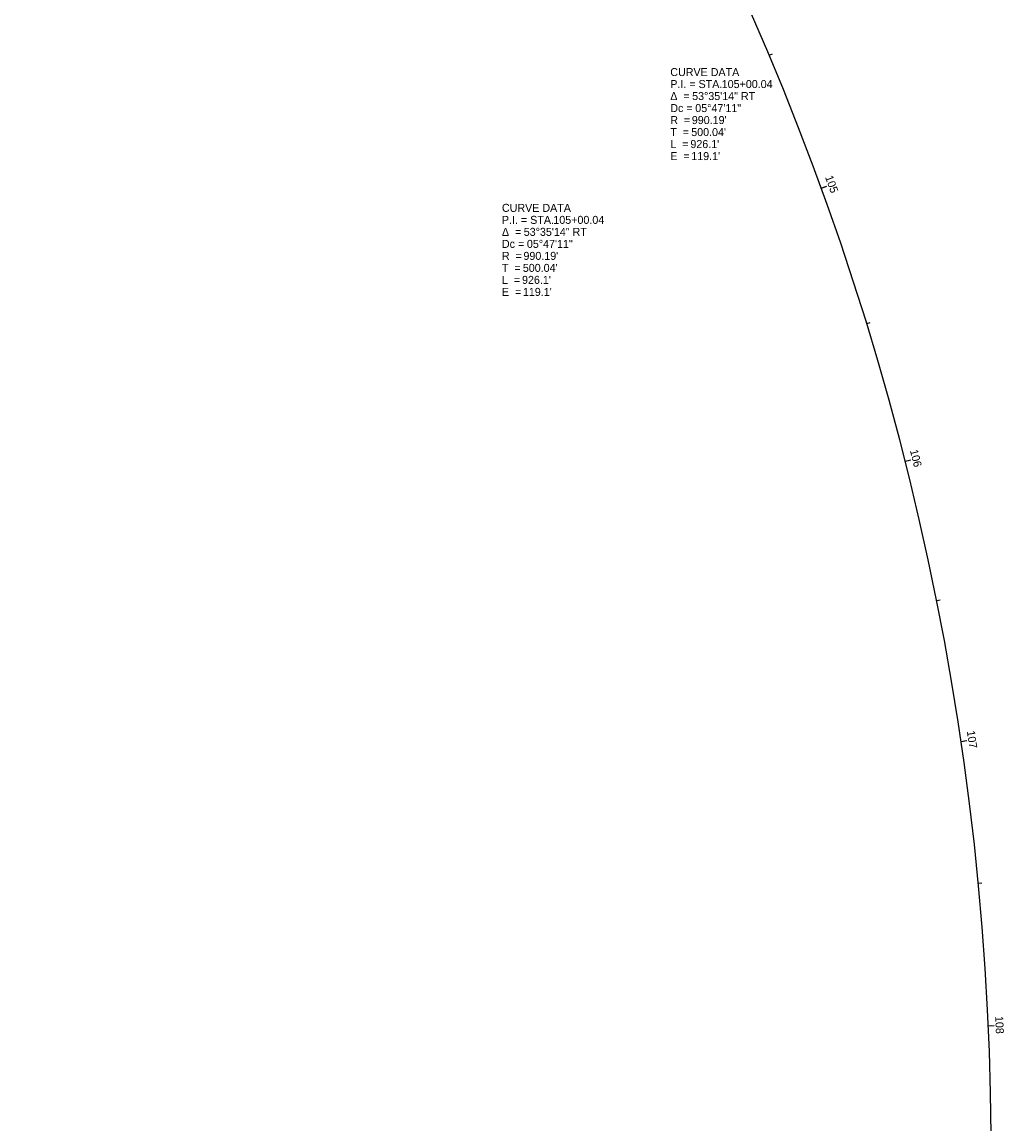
# Model space of a CAD drawing. Extents: x 1392427 to 1392809, y 435950 to 439080.
# Drawn here: x 1392427.6 to 1392771.2, y 438309.3 to 438694.9 of the extents above; entities that cross this region are included whole.
import ezdxf

# ---------------------------------------------------------------- set-up
doc = ezdxf.new("R2010")
doc.units = 0
for name, color, linetype in [('Default', 7, 'Continuous'), ('PV_X_Curb', 7, 'Continuous'), ('PV_X_EOP', 7, 'Continuous'), ('RD_X_Cells', 7, 'Continuous'), ('RW_X_CL', 7, 'Continuous'), ('RW_X_CL_100_Curve_Data', 7, 'Continuous'), ('RW_X_CL_100_Stations', 7, 'Continuous'), ('SV_X_Mon_Cells_Found', 7, 'Continuous'), ('SV_X_Random_Point', 7, 'Continuous'), ('VG_X_Cells', 7, 'Continuous')]:
    doc.layers.add(name, color=color, linetype=linetype)

msp = doc.modelspace()

# ---------------------------------------------------------------- linework, layer by layer
at = {"layer": 'Default'}
msp.add_arc((1391776.54, 438298.83), 990.19, 355.29887, 48.88602, dxfattribs=at)
at = {"layer": 'PV_X_Curb'}
for p, q in [((1392707.29, 438636.75), (1392709.17, 438637.43)), ((1392736.61, 438541.19), (1392737.78, 438541.49)), ((1392756.16, 438443.17), (1392757.34, 438443.34)), ((1392765.72, 438343.67), (1392766.92, 438343.72))]:
    msp.add_line(p, q, dxfattribs=at)
at = {"layer": 'RD_X_Cells'}
msp.add_line((1392707.29, 438636.75), (1392708.41, 438637.16), dxfattribs=at)
at = {"layer": 'RW_X_CL'}
msp.add_arc((1391776.54, 438298.83), 990.19, 355.29887, 48.88602, dxfattribs=at)
msp.add_arc((1391776.54, 438298.83), 990.19, 355.29887, 48.88602, dxfattribs=at)
at = {"layer": 'RW_X_CL_100_Stations'}
for p, q in [((1392689.04, 438683.3), (1392690.15, 438683.77)), ((1392707.29, 438636.75), (1392709.17, 438637.43)), ((1392723.16, 438589.34), (1392724.3, 438589.7)), ((1392736.61, 438541.19), (1392738.55, 438541.68)), ((1392747.62, 438492.43), (1392748.8, 438492.66)), ((1392756.16, 438443.17), (1392758.13, 438443.46)), ((1392762.19, 438393.54), (1392763.39, 438393.65)), ((1392765.72, 438343.67), (1392767.71, 438343.76))]:
    msp.add_line(p, q, dxfattribs=at)
at = {"layer": 'SV_X_Mon_Cells_Found'}
for p, q in [((1392707.29, 438636.75), (1392709.17, 438637.43)), ((1392736.61, 438541.19), (1392737.78, 438541.49)), ((1392756.16, 438443.17), (1392757.34, 438443.34)), ((1392765.72, 438343.67), (1392766.92, 438343.72))]:
    msp.add_line(p, q, dxfattribs=at)

# ---------------------------------------------------------------- texts
at = {"layer": 'PV_X_Curb'}
msp.add_text('105', height=2.8, rotation=289.9544, dxfattribs=at).set_placement((1392708.54, 438640.62))
at = {"layer": 'PV_X_EOP'}
for s, p in [('CURVE DATA', (1392595.53, 438628.46)), ('P.I. = STA. ', (1392595.53, 438624.26)), ('105+00.04', (1392613.52, 438624.26)), ('Δ  = ', (1392595.53, 438620.06)), ('53°35\'14" RT', (1392603.17, 438620.06)), ('Dc = ', (1392595.53, 438615.86)), ('05°47\'11"', (1392604.27, 438615.86)), ('R  = ', (1392595.53, 438611.66)), ("990.19'", (1392603.06, 438611.66)), ('T  = ', (1392595.53, 438607.46)), ("500.04'", (1392602.84, 438607.46)), ('L  = ', (1392595.53, 438603.26)), ("926.1'", (1392602.56, 438603.26)), ('E  = ', (1392595.53, 438599.06)), ("119.1'", (1392602.87, 438599.06))]:
    msp.add_text(s, height=2.8, dxfattribs=at).set_placement(p)
at = {"layer": 'RW_X_CL_100_Curve_Data'}
for s, p in [('CURVE DATA', (1392654.43, 438675.98)), ('P.I. = STA. ', (1392654.43, 438671.78)), ('105+00.04', (1392672.42, 438671.78)), ('Δ  = ', (1392654.43, 438667.58)), ('53°35\'14" RT', (1392662.07, 438667.58)), ('Dc = ', (1392654.43, 438663.38)), ('05°47\'11"', (1392663.17, 438663.38)), ('R  = ', (1392654.43, 438659.18)), ("990.19'", (1392661.96, 438659.18)), ("500.04'", (1392661.75, 438654.98)), ('T  = ', (1392654.43, 438654.98)), ('L  = ', (1392654.43, 438650.78)), ("926.1'", (1392661.46, 438650.78)), ('E  = ', (1392654.43, 438646.58)), ("119.1'", (1392661.77, 438646.58))]:
    msp.add_text(s, height=2.8, dxfattribs=at).set_placement(p)
at = {"layer": 'RW_X_CL_100_Stations'}
for s, rotation, p in [('105', 289.9544, (1392708.54, 438640.62)), ('106', 284.1681, (1392738.24, 438544.96)), ('107', 278.3818, (1392758.16, 438446.74)), ('108', 272.5955, (1392768.07, 438347.03))]:
    msp.add_text(s, height=2.8, rotation=rotation, dxfattribs=at).set_placement(p)
at = {"layer": 'SV_X_Mon_Cells_Found'}
msp.add_text('105', height=2.8, rotation=289.9544, dxfattribs=at).set_placement((1392708.54, 438640.62))
at = {"layer": 'SV_X_Random_Point'}
for s, p in [('CURVE DATA', (1392595.53, 438628.46)), ('P.I. = STA. ', (1392595.53, 438624.26)), ('105+00.04', (1392613.52, 438624.26)), ('Δ  = ', (1392595.53, 438620.06)), ('53°35\'14" RT', (1392603.17, 438620.06)), ('Dc = ', (1392595.53, 438615.86)), ('05°47\'11"', (1392604.27, 438615.86)), ('R  = ', (1392595.53, 438611.66)), ("990.19'", (1392603.06, 438611.66)), ('T  = ', (1392595.53, 438607.46)), ("500.04'", (1392602.84, 438607.46)), ('L  = ', (1392595.53, 438603.26)), ("926.1'", (1392602.56, 438603.26)), ('E  = ', (1392595.53, 438599.06)), ("119.1'", (1392602.87, 438599.06))]:
    msp.add_text(s, height=2.8, dxfattribs=at).set_placement(p)
at = {"layer": 'VG_X_Cells'}
for s, p in [('CURVE DATA', (1392595.53, 438628.46)), ('P.I. = STA. ', (1392595.53, 438624.26)), ('105+00.04', (1392613.52, 438624.26)), ('Δ  = ', (1392595.53, 438620.06)), ('53°35\'14" RT', (1392603.17, 438620.06)), ('Dc = ', (1392595.53, 438615.86)), ('05°47\'11"', (1392604.27, 438615.86)), ('R  = ', (1392595.53, 438611.66)), ("990.19'", (1392603.06, 438611.66)), ('T  = ', (1392595.53, 438607.46)), ("500.04'", (1392602.84, 438607.46)), ('L  = ', (1392595.53, 438603.26)), ("926.1'", (1392602.56, 438603.26)), ('E  = ', (1392595.53, 438599.06)), ("119.1'", (1392602.87, 438599.06))]:
    msp.add_text(s, height=2.8, dxfattribs=at).set_placement(p)

doc.saveas('drawing.dxf')
